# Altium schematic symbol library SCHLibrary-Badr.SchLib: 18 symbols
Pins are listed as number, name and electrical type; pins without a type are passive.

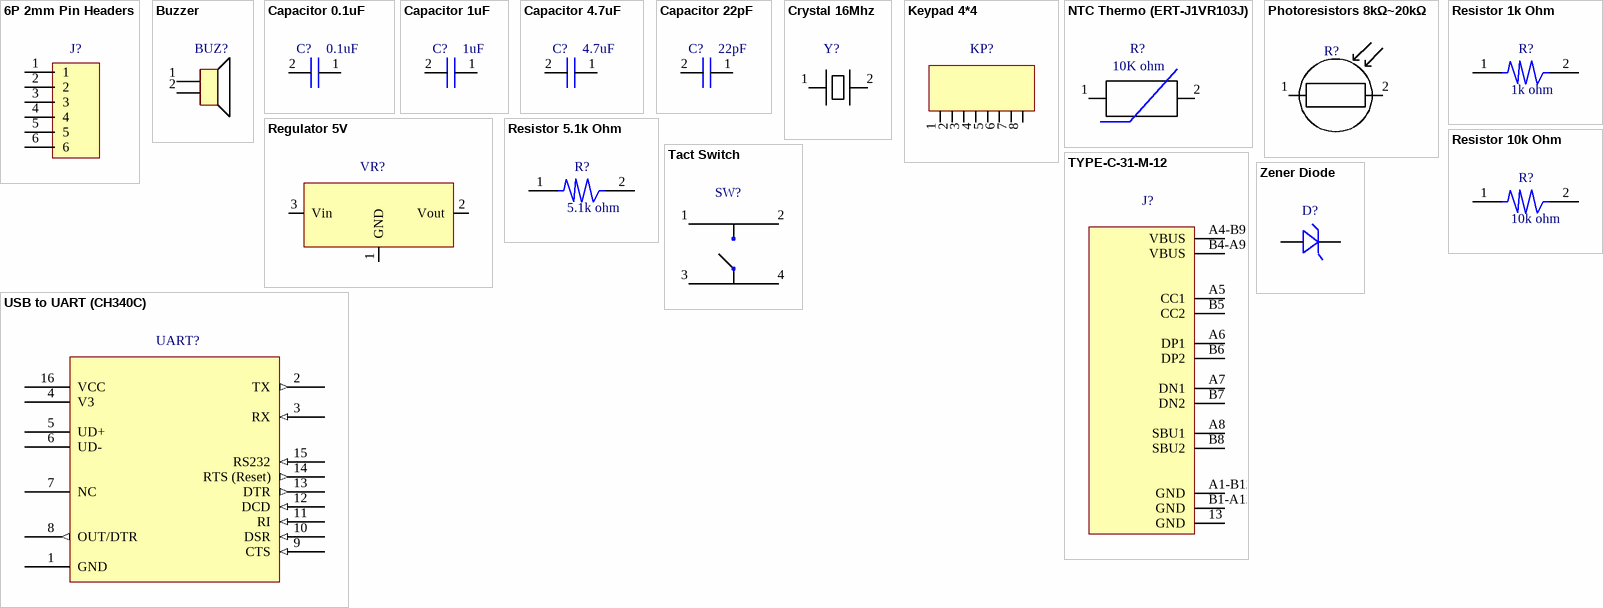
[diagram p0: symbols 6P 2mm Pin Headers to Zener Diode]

## 6P 2mm Pin Headers
designator J?
Connector Header Through Hole 6 position 0.079" (2.00mm); Manufacturer: TE Connectivity AMP Connectors; Manufacturer Part Number: 2355172-6
footprint 6P 2mm Pin header
pins: 1, 2, 3, 4, 5, 6

## Buzzer
designator BUZ?
BUZZER PIEZO 1.5V 12X12MM SMD / Buzzers Transducer, Externally Driven Piezo 1.5 V 4kHz 84dB @ 1.5V, 10cm Surface Mount Solder Pads; Manufacturer: Murata Electronics; Manufacturer Product Number: PKLCS1212E4001-R1
footprint Buzzer
pins: 1, 2

## Capacitor 0.1uF
designator C?, comment 0.1uF
50V 100nF X7R ±10% 0603 Multilayer Ceramic Capacitors MLCC - SMD/SMT ROHS; Manufacturer: YAGEO; Manufacturer Product Number: CC0603KRX7R9BB104
footprint Capacitor 0603 SMD
pins: 1, 2

## Capacitor 1uF
designator C?, comment 1uF
16V 1uF X5R ±10% 0603 Multilayer Ceramic Capacitors MLCC - SMD/SMT ROHS; Manufacturer: Samsung Electro-Mechanics; Manufacturer Product Number: CL10A105KO8NNNC
footprint Capacitor 0603 SMD
pins: 1, 2

## Capacitor 4.7uF
designator C?, comment 4.7uF
10V 4.7uF X5R ±10% 0603 Multilayer Ceramic Capacitors MLCC - SMD/SMT ROHS; Manufacturer: Samsung Electro-Mechanics; Manufacturer Product Number: CL10A475KP8NNNC
footprint Capacitor 0603 SMD
pins: 1, 2

## Capacitor 22pF
designator C?, comment 22pF
50V 22pF NP0 ±5% 0603 Multilayer Ceramic Capacitors MLCC - SMD/SMT ROHS; Manufacturer: YAGEO; Manufacturer Product Number: CC0603JRNPO9BN220
footprint Capacitor 0603 SMD
pins: 1, 2

## Crystal 16Mhz
designator Y?
16 MHz ±30ppm Crystal 20pF 50 Ohms HC-49/US; Manufacturer: ECS Inc.; Manufacturer Product Number: ECS-160-20-3X-TR
footprint Crystal 16Mhz
pins: 1, 2

## Keypad 4*4
designator KP?
SWITCH KEYPAD 16KEY 0.005A 12V / Keypad Switch 16 Polymer Keys Conductive Rubber Contacts Matrix Output Non-Illuminated 0.005A @ 12VDC; Manufacturer: Grayhill Inc.; Manufacturer Product Number: 96BB2-056-F
pins: 1, 2, 3, 4, 5, 6, 7, 8

## NTC Thermo (ERT-J1VR103J)
designator R?, comment 10K ohm
THERMISTOR NTC 10KOHM 4250K 0603; Manufacturer: Panasonic Electronic Components; Manufacturer Product Number: ERT-J1VR103J
footprint Resistor 0603 SMD
pins: 1, 2

## Photoresistors 8kΩ~20kΩ
designator R?
8kΩ~20kΩ 540nm 1MΩ Plugin,P=3mm Photoresistors ROHS; Manufacturer: Senba Sensing Tech; Manufacturer Product Number: GL5528
footprint Photoresistor GL5528
pins: 1, 2

## Regulator 5V
designator VR?
1A Fixed 5V Positive electrode 18V SOT-89 Voltage Regulators - Linear, Low Drop Out (LDO) Regulators ROHS; Manufacturer: MSKSEMI; Manufacturer Product Number: AMS1117-5.0V
footprint Regulator 5V AMS1117
pins: 1 GND, 2 Vout, 3 Vin

## Resistor 1k Ohm
designator R?, comment 1k ohm
100mW Thick Film Resistors 75V ±100ppm/℃ ±1% 1kΩ 0603 Chip Resistor - Surface Mount ROHS; Manufacturer: UNI-ROYAL(Uniroyal Elec); Manufacturer Product Number: 0603WAF1001T5E
footprint Resistor 0603 SMD
pins: 1, 2

## Resistor 5.1k Ohm
designator R?, comment 5.1k ohm
100mW Thick Film Resistors 75V ±100ppm/℃ ±1% 5.1kΩ 0603 Chip Resistor - Surface Mount ROHS; Manufacturer: UNI-ROYAL(Uniroyal Elec); Manufacturer Product Number: 0603WAF5101T5E
footprint Resistor 0603 SMD
pins: 1, 2

## Resistor 10k Ohm
designator R?, comment 10k ohm
100mW Thick Film Resistors 75V ±100ppm/℃ ±1% 10kΩ 0603 Chip Resistor - Surface Mount ROHS; Manufacturer: UNI-ROYAL(Uniroyal Elec); Manufacturer Product Number: 0603WAF1002T5E
footprint Resistor 0603 SMD
pins: 1, 2

## Tact Switch
designator SW?
SWITCH TACTILE SPST-NO 0.05A 12V / Tactile Switch SPST-NO Top Actuated Surface Mount; Manufacturer: C&K; Manufacturer Product Number: PTS 647 SN50 SMTR2 LFS
footprint Tact Switch
pins: 1, 2, 3, 4

## TYPE-C-31-M-12
designator J?  (value not drawn)
5A 1 16P Female Type-C SMD USB Connectors ROHS; Manufacturer: Korean Hroparts Elec; Manufacturer Product Number: TYPE-C-31-M-12
footprint USB TYPE C-31-M-12
pins: 13 GND, A1-B12 GND, A4-B9 VBUS, A5 CC1, A6 DP1, A7 DN1, A8 SBU1, B1-A12 GND, B4-A9 VBUS, B5 CC2, B6 DP2, B7 DN2, B8 SBU2

## USB to UART (CH340C)
designator UART?
2Mbps Transceiver USB 2.0 SOP-16 USB Converters ROHS; Manufacturer: WCH(Jiangsu Qin Heng); Manufacturer Product Number: CH340C
footprint (USB-UART) CH340C
pins: 1 GND, 2 TX (out), 3 RX (in), 4 V3, 5 UD+, 6 UD-, 7 NC, 8 OUT/DTR (out), 9 CTS (in), 10 DSR (in), 11 RI (in), 12 DCD (in), 13 DTR (out), 14 RTS (Reset) (out), 15 RS232 (in), 16 VCC

## Zener Diode
designator D?
DIODE ZENER 5.1V 500MW SOD123; Manufacturer: Diodes Incorporated; Manufacturer Product Number: MMSZ5231B-7-F
footprint Zener Diode
pins: 1, 2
